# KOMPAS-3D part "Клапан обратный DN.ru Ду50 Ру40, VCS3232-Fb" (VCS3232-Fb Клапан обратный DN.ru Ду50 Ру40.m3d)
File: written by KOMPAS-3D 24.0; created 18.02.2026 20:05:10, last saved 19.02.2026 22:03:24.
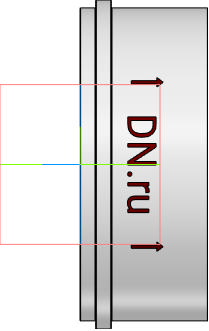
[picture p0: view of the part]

Document properties: Автор: R2D2; Полное имя файла: D:\Работа\Клапаны обратные\VCS3232-Fb Клапан обратный DN.ru Ду15-100\DN50\VCS3232-Fb Клапан обратный DN.ru Ду50 Ру40.m3d

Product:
- Body: Тело 1  | qty 1
    Масса: 0.806125
- Body: Тело 2  | qty 1
    Масса: 0.317881
- Part/product: Клапан обратный DN.ru Ду50 Ру40  | designation VCS3232-Fb
    Масса: 0.981
    Раздел спецификации: Прочие изделия
    Примечание: D100-03710
    additional columns: 1; D100-03710

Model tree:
1. Операция без истории:1
2. Операция без истории:2

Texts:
  Точка начала. Х
  Точка начала. Y
  Точка начала. Z
  VCS3232-Fb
